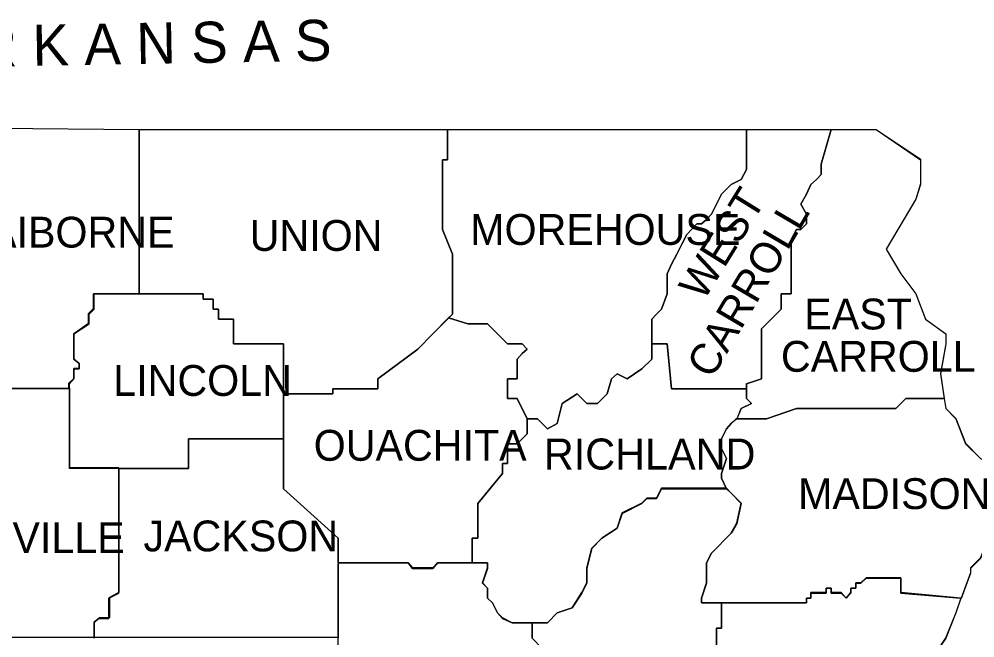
# Model space of a CAD drawing. Extents: x 0.19 to 2.82, y 0.04 to 1.79.
# Drawn here: x 2.2917 to 2.4368, y 1.6727 to 1.7666 of the extents above; entities that cross this region are included whole.
import ezdxf

# ---------------------------------------------------------------- set-up
doc = ezdxf.new("R2010")
doc.units = 0
for name, color, linetype in [('Dist04', 7, 'Continuous'), ('Dist05', 7, 'Continuous'), ('Dist08', 7, 'Continuous'), ('Dist58', 7, 'Continuous'), ('Standard Info', 7, 'Continuous')]:
    doc.layers.add(name, color=color, linetype=linetype)

msp = doc.modelspace()

# ---------------------------------------------------------------- linework, layer by layer
at = {"layer": 'Dist04'}
msp.add_line((2.27282, 1.75017), (2.3099, 1.74983), dxfattribs=at)
for points in [[(2.3099, 1.74983), (2.3099, 1.72492)], [(2.3099, 1.72492), (2.30299, 1.72492), (2.30299, 1.72267), (2.30224, 1.72192), (2.30224, 1.72042), (2.29999, 1.71883), (2.29999, 1.71508), (2.30082, 1.71433), (2.30082, 1.71358), (2.29999, 1.71358), (2.29999, 1.71208), (2.29924, 1.71133), (2.29924, 1.7105)], [(2.29932, 1.71058), (2.29932, 1.6985), (2.30682, 1.6985)], [(2.30682, 1.6985), (2.30682, 1.67958), (2.3054, 1.67883), (2.3054, 1.6765), (2.3054, 1.67575), (2.3039, 1.67575), (2.30307, 1.67508), (2.30307, 1.67275)], [(2.30307, 1.67275), (2.27665, 1.67275)]]:
    msp.add_lwpolyline(points, dxfattribs=at)
at = {"layer": 'Dist05'}
for p, q in [((2.3099, 1.74983), (2.35674, 1.74983)), ((2.35674, 1.74983), (2.40215, 1.74983)), ((2.40215, 1.74983), (2.41499, 1.74983)), ((2.41499, 1.74983), (2.42182, 1.74983))]:
    msp.add_line(p, q, dxfattribs=at)
for points in [[(2.3099, 1.72492), (2.3099, 1.74983)], [(2.42182, 1.74983), (2.42857, 1.74533), (2.42857, 1.74158), (2.42782, 1.73925), (2.42332, 1.73167), (2.42557, 1.72792), (2.42782, 1.72492), (2.42932, 1.72108), (2.4324, 1.71883), (2.4324, 1.71733), (2.43157, 1.71283), (2.43215, 1.709)], [(2.29924, 1.7105), (2.29924, 1.71133), (2.29999, 1.71208), (2.29999, 1.71358), (2.30082, 1.71358), (2.30082, 1.71433), (2.29999, 1.71508), (2.29999, 1.71883), (2.30224, 1.72042), (2.30224, 1.72192), (2.30299, 1.72267), (2.30299, 1.72492), (2.3099, 1.72492)], [(2.30682, 1.6985), (2.29932, 1.6985), (2.29932, 1.71058)], [(2.43215, 1.709), (2.4324, 1.7075), (2.4339, 1.706), (2.4354, 1.70225), (2.43765, 1.69992), (2.43915, 1.69925), (2.44065, 1.69542), (2.43999, 1.69083), (2.43765, 1.68483), (2.43615, 1.68333), (2.43615, 1.68258), (2.43474, 1.67875)], [(2.30307, 1.67275), (2.30307, 1.67508), (2.3039, 1.67575), (2.3054, 1.67575), (2.3054, 1.6765), (2.3054, 1.67883), (2.30682, 1.67958), (2.30682, 1.6985)], [(2.39907, 1.69542), (2.38924, 1.69542), (2.38849, 1.69392), (2.38699, 1.69392), (2.38624, 1.69317), (2.38324, 1.69167), (2.38249, 1.68933), (2.38015, 1.68783), (2.37865, 1.68633), (2.3779, 1.68333), (2.3779, 1.68108), (2.37715, 1.67958), (2.37565, 1.67725), (2.3734, 1.6765), (2.3719, 1.675), (2.36957, 1.675), (2.36807, 1.675), (2.36657, 1.675), (2.36507, 1.67575), (2.36432, 1.6765), (2.36357, 1.678), (2.36282, 1.67875), (2.36282, 1.68025), (2.36207, 1.68108), (2.36282, 1.68333), (2.36282, 1.68408), (2.36049, 1.68408)], [(2.41124, 1.678), (2.39532, 1.678), (2.39532, 1.67875), (2.39607, 1.68108), (2.39607, 1.68258), (2.39607, 1.68408), (2.39682, 1.68558), (2.39982, 1.68858), (2.40065, 1.69017), (2.40132, 1.69317), (2.39982, 1.69467), (2.39907, 1.69542)], [(2.36049, 1.68408), (2.35524, 1.68408), (2.35449, 1.68333), (2.3514, 1.68333), (2.35074, 1.68408), (2.34015, 1.68408)], [(2.34015, 1.684), (2.34015, 1.67275)], [(2.42557, 1.67958), (2.42557, 1.68183), (2.42032, 1.68183), (2.41949, 1.68108), (2.41874, 1.68108), (2.41874, 1.68025), (2.41799, 1.68025), (2.41799, 1.67958), (2.41724, 1.67875), (2.41649, 1.67958), (2.41499, 1.67958), (2.41499, 1.68025), (2.41424, 1.68025), (2.41424, 1.67958), (2.4119, 1.67958), (2.4119, 1.67875), (2.41124, 1.67875), (2.41124, 1.678)], [(2.43465, 1.67875), (2.42557, 1.67958)], [(2.34015, 1.67275), (2.30307, 1.67275)]]:
    msp.add_lwpolyline(points, dxfattribs=at)
at = {"layer": 'Dist08'}
for points in [[(2.30307, 1.67275), (2.27665, 1.67275)], [(2.34015, 1.67275), (2.30307, 1.67275)], [(2.34015, 1.65458), (2.34015, 1.67275)]]:
    msp.add_lwpolyline(points, dxfattribs=at)
at = {"layer": 'Dist58'}
msp.add_line((2.43465, 1.67875), (2.43465, 1.67875), dxfattribs=at)
for points in [[(2.36049, 1.68408), (2.36282, 1.68408), (2.36282, 1.68333), (2.36207, 1.68108), (2.36282, 1.68025), (2.36282, 1.67875), (2.36357, 1.678), (2.36432, 1.6765), (2.36507, 1.67575), (2.36657, 1.675), (2.36807, 1.675), (2.36957, 1.675), (2.3719, 1.675), (2.3734, 1.6765), (2.37565, 1.67725), (2.37715, 1.67958), (2.3779, 1.68108), (2.3779, 1.68333), (2.37865, 1.68633), (2.38015, 1.68783), (2.38249, 1.68933), (2.38324, 1.69167), (2.38624, 1.69317), (2.38699, 1.69392), (2.38849, 1.69392), (2.38924, 1.69542), (2.39907, 1.69542)], [(2.39907, 1.69542), (2.39982, 1.69467), (2.40132, 1.69317), (2.40065, 1.69017), (2.39982, 1.68858), (2.39682, 1.68558), (2.39607, 1.68408), (2.39607, 1.68258), (2.39607, 1.68108), (2.39532, 1.67875), (2.39532, 1.678), (2.41124, 1.678)], [(2.34015, 1.68408), (2.35074, 1.68408), (2.3514, 1.68333), (2.35449, 1.68333), (2.35524, 1.68408), (2.36049, 1.68408)], [(2.34015, 1.67275), (2.34015, 1.684)], [(2.41124, 1.678), (2.41124, 1.67875), (2.4119, 1.67875), (2.4119, 1.67958), (2.41424, 1.67958), (2.41424, 1.68025), (2.41499, 1.68025), (2.41499, 1.67958), (2.41649, 1.67958), (2.41724, 1.67875), (2.41799, 1.67958), (2.41799, 1.68025), (2.41874, 1.68025), (2.41874, 1.68108), (2.41949, 1.68108), (2.42032, 1.68183), (2.42557, 1.68183), (2.42557, 1.67958)], [(2.42557, 1.67958), (2.43465, 1.67875)], [(2.43465, 1.67875), (2.4339, 1.6765), (2.4324, 1.67275), (2.4309, 1.6705), (2.42782, 1.66517), (2.42482, 1.66142), (2.42182, 1.65758), (2.41799, 1.65308), (2.41424, 1.64933), (2.41274, 1.647), (2.40899, 1.63942)], [(2.34015, 1.65458), (2.34015, 1.67275)]]:
    msp.add_lwpolyline(points, dxfattribs=at)
at = {"layer": 'Standard Info'}
for p, q in [((2.27282, 1.75017), (2.3099, 1.74983)), ((2.3099, 1.74983), (2.35674, 1.74983)), ((2.35674, 1.74983), (2.40215, 1.74983)), ((2.40215, 1.74983), (2.41499, 1.74983)), ((2.41499, 1.74983), (2.42182, 1.74983)), ((2.3569, 1.72125), (2.35749, 1.72183)), ((2.40057, 1.70592), (2.40049, 1.70592))]:
    msp.add_line(p, q, dxfattribs=at)
for points in [[(2.3099, 1.74983), (2.3099, 1.72492)], [(2.3099, 1.72492), (2.3099, 1.74983)], [(2.35674, 1.74983), (2.35674, 1.74525), (2.35599, 1.74525), (2.35599, 1.743), (2.35599, 1.73467), (2.35749, 1.73092), (2.35749, 1.72792), (2.35749, 1.72492), (2.35749, 1.72183), (2.35674, 1.72108), (2.35449, 1.71883), (2.35224, 1.7165), (2.34615, 1.712), (2.34615, 1.7105), (2.33932, 1.7105), (2.33932, 1.70975), (2.33182, 1.70975)], [(2.35749, 1.72183), (2.35749, 1.72492), (2.35749, 1.72792), (2.35749, 1.73092), (2.35599, 1.73467), (2.35599, 1.743), (2.35599, 1.74525), (2.35674, 1.74525), (2.35674, 1.74983)], [(2.38774, 1.71733), (2.38774, 1.71883), (2.38774, 1.72108), (2.38849, 1.72183), (2.38924, 1.72258), (2.39007, 1.72492), (2.39007, 1.72792), (2.39074, 1.72942), (2.39157, 1.73092), (2.39232, 1.73242), (2.39307, 1.73392), (2.39457, 1.7355), (2.39532, 1.7355), (2.39607, 1.73617), (2.39682, 1.737), (2.39757, 1.7385), (2.39832, 1.74), (2.39982, 1.7415), (2.40132, 1.74225), (2.40215, 1.74375), (2.40215, 1.74458), (2.40215, 1.74983)], [(2.40215, 1.74983), (2.40215, 1.74458), (2.40215, 1.74375), (2.40132, 1.74225), (2.39982, 1.7415), (2.39832, 1.74), (2.39757, 1.7385), (2.39682, 1.737), (2.39607, 1.73617), (2.39532, 1.7355), (2.39457, 1.7355), (2.39307, 1.73392), (2.39232, 1.73242), (2.39157, 1.73092), (2.39074, 1.72942), (2.39007, 1.72792), (2.39007, 1.72492), (2.38924, 1.72258), (2.38849, 1.72183), (2.38774, 1.72108), (2.38774, 1.71883), (2.38774, 1.71733)], [(2.38774, 1.71733), (2.38774, 1.71883), (2.38774, 1.72108), (2.38849, 1.72183), (2.38924, 1.72258), (2.39007, 1.72492), (2.39007, 1.72792), (2.39074, 1.72942), (2.39157, 1.73092), (2.39232, 1.73242), (2.39307, 1.73392), (2.39457, 1.7355), (2.39532, 1.7355), (2.39607, 1.73617), (2.39682, 1.737), (2.39757, 1.7385), (2.39832, 1.74), (2.39982, 1.7415), (2.40132, 1.74225), (2.40215, 1.74375), (2.40215, 1.74458), (2.40215, 1.74983)], [(2.40074, 1.70608), (2.40132, 1.7075), (2.4029, 1.70825), (2.40215, 1.709), (2.40215, 1.7105), (2.40215, 1.71125), (2.4044, 1.712), (2.4044, 1.71275), (2.4044, 1.7135), (2.4044, 1.71433), (2.4044, 1.71583), (2.4044, 1.71733), (2.4044, 1.71958), (2.40515, 1.72033), (2.4059, 1.72108), (2.40665, 1.72183), (2.4074, 1.72258), (2.4074, 1.72492), (2.4089, 1.72492), (2.4089, 1.73317), (2.40974, 1.73467), (2.4104, 1.73467), (2.41124, 1.7355), (2.41124, 1.737), (2.4104, 1.7385), (2.41124, 1.74), (2.4119, 1.7415), (2.41274, 1.74225), (2.41349, 1.743), (2.41349, 1.74458), (2.41499, 1.74983)], [(2.41499, 1.74983), (2.41349, 1.74458), (2.41349, 1.743), (2.41274, 1.74225), (2.4119, 1.7415), (2.41124, 1.74), (2.4104, 1.7385), (2.41124, 1.737), (2.41124, 1.7355), (2.4104, 1.73467), (2.40974, 1.73467), (2.4089, 1.73317), (2.4089, 1.72492), (2.4074, 1.72492), (2.4074, 1.72258), (2.40665, 1.72183), (2.4059, 1.72108), (2.40515, 1.72033), (2.4044, 1.71958), (2.4044, 1.71733), (2.4044, 1.71583), (2.4044, 1.71433), (2.4044, 1.7135), (2.4044, 1.71275), (2.4044, 1.712), (2.40215, 1.71125), (2.40215, 1.7105)], [(2.42182, 1.74983), (2.42857, 1.74525), (2.42857, 1.7415), (2.42782, 1.73925), (2.42332, 1.73167), (2.42557, 1.72792), (2.42782, 1.72492), (2.42932, 1.72108), (2.4324, 1.71883), (2.4324, 1.71733), (2.43157, 1.71275), (2.43215, 1.709)], [(2.3099, 1.72492), (2.30299, 1.72492), (2.30299, 1.72258), (2.30224, 1.72183), (2.30224, 1.72033), (2.29999, 1.71883), (2.29999, 1.715), (2.30082, 1.71433), (2.30082, 1.7135), (2.29999, 1.7135), (2.29999, 1.712), (2.29924, 1.71125), (2.29924, 1.7105)], [(2.29932, 1.7105), (2.29932, 1.71125), (2.29999, 1.712), (2.29999, 1.7135), (2.30082, 1.7135), (2.30082, 1.71433), (2.29999, 1.715), (2.29999, 1.71883), (2.30232, 1.72033), (2.30232, 1.72183), (2.30307, 1.72258), (2.30307, 1.72492), (2.3099, 1.72492)], [(2.29932, 1.7105), (2.29932, 1.71125), (2.29999, 1.712), (2.29999, 1.7135), (2.30082, 1.7135), (2.30082, 1.71433), (2.29999, 1.715), (2.29999, 1.71883), (2.30232, 1.72033), (2.30232, 1.72183), (2.30307, 1.72258), (2.30307, 1.72492), (2.3099, 1.72492)], [(2.33182, 1.70975), (2.33182, 1.71733), (2.32424, 1.71733), (2.32424, 1.72108), (2.32199, 1.72108), (2.32199, 1.72258), (2.32115, 1.72258), (2.32115, 1.72408), (2.31965, 1.72408), (2.31965, 1.72492), (2.3099, 1.72492)], [(2.3099, 1.72492), (2.31965, 1.72492), (2.31965, 1.72408), (2.32115, 1.72408), (2.32115, 1.72258), (2.32199, 1.72258), (2.32199, 1.72108), (2.32424, 1.72108), (2.32424, 1.71733), (2.33182, 1.71733), (2.33182, 1.70975), (2.33182, 1.70292)], [(2.33182, 1.70975), (2.33932, 1.70975), (2.33932, 1.7105), (2.34615, 1.7105), (2.34615, 1.712), (2.35224, 1.7165), (2.35449, 1.71883), (2.3569, 1.72125)], [(2.3569, 1.72125), (2.35982, 1.72033), (2.36282, 1.72033), (2.36432, 1.71883), (2.36582, 1.71733), (2.36807, 1.71733), (2.36882, 1.7165), (2.36807, 1.71583), (2.36732, 1.715), (2.36732, 1.712), (2.36582, 1.712), (2.36582, 1.709), (2.36732, 1.709), (2.36882, 1.70592), (2.36882, 1.70367), (2.36732, 1.70217), (2.36582, 1.70217), (2.36582, 1.69917), (2.36507, 1.69917), (2.36507, 1.69767), (2.36132, 1.69308), (2.36132, 1.68783), (2.36049, 1.68783), (2.36049, 1.68408)], [(2.36882, 1.70592), (2.36732, 1.709), (2.36582, 1.709), (2.36582, 1.712), (2.36732, 1.712), (2.36732, 1.715), (2.36807, 1.71583), (2.36882, 1.7165), (2.36807, 1.71733), (2.36582, 1.71733), (2.36432, 1.71883), (2.36282, 1.72033), (2.35982, 1.72033), (2.3569, 1.72125)], [(2.38774, 1.71733), (2.38774, 1.715), (2.38624, 1.7135), (2.38399, 1.712), (2.38249, 1.71275), (2.38165, 1.712), (2.38099, 1.70975), (2.37949, 1.70825), (2.3779, 1.70825), (2.3764, 1.70975), (2.37415, 1.70825), (2.3734, 1.70525), (2.3719, 1.70442), (2.3704, 1.70592), (2.36882, 1.70592)], [(2.36882, 1.70592), (2.3704, 1.70592), (2.3719, 1.70442), (2.3734, 1.70525), (2.37415, 1.70825), (2.3764, 1.70975), (2.3779, 1.70825), (2.37949, 1.70825), (2.38099, 1.70975), (2.38165, 1.712), (2.38249, 1.71275), (2.38399, 1.712), (2.38624, 1.7135), (2.38774, 1.715), (2.38774, 1.71733)], [(2.40215, 1.7105), (2.39074, 1.7105), (2.39007, 1.71733), (2.38774, 1.71733)], [(2.38774, 1.71733), (2.39007, 1.71733), (2.39074, 1.7105), (2.40215, 1.7105)], [(2.29924, 1.7105), (2.27765, 1.7105)], [(2.27774, 1.71058), (2.29932, 1.71058)], [(2.29932, 1.71058), (2.29932, 1.6985), (2.30682, 1.6985)], [(2.30682, 1.69842), (2.29932, 1.69842), (2.29932, 1.7105)], [(2.34015, 1.68408), (2.34015, 1.68783), (2.33182, 1.69533), (2.33182, 1.70292), (2.33182, 1.70975)], [(2.40215, 1.7105), (2.40215, 1.709), (2.4029, 1.70825), (2.40132, 1.7075), (2.40065, 1.70592), (2.39982, 1.70525), (2.39907, 1.70442), (2.39832, 1.70292), (2.39832, 1.70217), (2.39832, 1.70142), (2.39907, 1.69992), (2.39832, 1.69767), (2.39832, 1.69692), (2.39907, 1.69533)], [(2.43215, 1.709), (2.42632, 1.709), (2.42482, 1.7075), (2.40974, 1.7075), (2.40515, 1.70592), (2.40049, 1.70592)], [(2.40049, 1.70592), (2.40515, 1.70592), (2.40974, 1.7075), (2.42482, 1.7075), (2.42632, 1.709), (2.43215, 1.709)], [(2.43215, 1.709), (2.4324, 1.7075), (2.4339, 1.70592), (2.4354, 1.70217), (2.43765, 1.69992), (2.43915, 1.69917), (2.44065, 1.69533), (2.43999, 1.69083), (2.43765, 1.68475), (2.43615, 1.68325), (2.43615, 1.6825), (2.43474, 1.67867)], [(2.36049, 1.68408), (2.36049, 1.68783), (2.36132, 1.68783), (2.36132, 1.69308), (2.36507, 1.69767), (2.36507, 1.69917), (2.36582, 1.69917), (2.36582, 1.70217), (2.36732, 1.70217), (2.36882, 1.70367), (2.36882, 1.70592)], [(2.39907, 1.69533), (2.39832, 1.69692), (2.39832, 1.69767), (2.39907, 1.69992), (2.39832, 1.70142), (2.39832, 1.70217), (2.39832, 1.70292), (2.39907, 1.70442), (2.39982, 1.70525), (2.40057, 1.70592)], [(2.33182, 1.70292), (2.3174, 1.70292), (2.3174, 1.69842), (2.30682, 1.69842)], [(2.30682, 1.69842), (2.3174, 1.69842), (2.3174, 1.70292), (2.33182, 1.70292)], [(2.33182, 1.70292), (2.33182, 1.69533), (2.34015, 1.68783), (2.34015, 1.68408)], [(2.30682, 1.6985), (2.30682, 1.67958), (2.3054, 1.67875), (2.3054, 1.6765), (2.3054, 1.67575), (2.3039, 1.67575), (2.30307, 1.675), (2.30307, 1.67267)], [(2.30307, 1.67267), (2.30307, 1.675), (2.30382, 1.67567), (2.30532, 1.67567), (2.30532, 1.6765), (2.30532, 1.67875), (2.30682, 1.6795), (2.30682, 1.69842)], [(2.39907, 1.69533), (2.38924, 1.69533), (2.38849, 1.69383), (2.38699, 1.69383), (2.38624, 1.69308), (2.38324, 1.69158), (2.38249, 1.68933), (2.38015, 1.68783), (2.37865, 1.68625), (2.3779, 1.68325), (2.3779, 1.681), (2.37715, 1.6795), (2.37565, 1.67725), (2.3734, 1.6765), (2.3719, 1.675), (2.36957, 1.675), (2.36807, 1.675), (2.36657, 1.675), (2.36507, 1.67567), (2.36432, 1.6765), (2.36357, 1.678), (2.36282, 1.67875), (2.36282, 1.68025), (2.36207, 1.681), (2.36282, 1.68325), (2.36282, 1.68408), (2.36049, 1.68408)], [(2.36957, 1.675), (2.3719, 1.675), (2.3734, 1.6765), (2.37565, 1.67725), (2.37715, 1.6795), (2.3779, 1.681), (2.3779, 1.68325), (2.37865, 1.68625), (2.38015, 1.68783), (2.38249, 1.68933), (2.38324, 1.69158), (2.38624, 1.69308), (2.38699, 1.69383), (2.38849, 1.69383), (2.38924, 1.69533), (2.39907, 1.69533)], [(2.41124, 1.678), (2.39532, 1.678), (2.39532, 1.67875), (2.39607, 1.681), (2.39607, 1.6825), (2.39607, 1.68408), (2.39682, 1.68558), (2.39982, 1.68858), (2.40065, 1.69008), (2.40132, 1.69308), (2.39982, 1.69467), (2.39907, 1.69533)], [(2.39907, 1.69533), (2.39982, 1.69467), (2.40132, 1.69308), (2.40065, 1.69008), (2.39982, 1.68858), (2.39682, 1.68558), (2.39607, 1.68408), (2.39607, 1.6825), (2.39607, 1.681), (2.39532, 1.67875), (2.39532, 1.678), (2.39832, 1.678)], [(2.36049, 1.68408), (2.35524, 1.68408), (2.35449, 1.68325), (2.3514, 1.68325), (2.35074, 1.68408), (2.34015, 1.68408)], [(2.34015, 1.68408), (2.35074, 1.68408), (2.3514, 1.68325), (2.35449, 1.68325), (2.35524, 1.68408), (2.36282, 1.68408), (2.36282, 1.68325), (2.36207, 1.681), (2.36282, 1.68025), (2.36282, 1.67875), (2.36357, 1.678), (2.36432, 1.6765), (2.36507, 1.67567), (2.36657, 1.675), (2.36807, 1.675), (2.36957, 1.675)], [(2.34015, 1.68392), (2.34015, 1.67267)], [(2.34015, 1.67267), (2.34015, 1.68383)], [(2.42557, 1.6795), (2.42557, 1.68175), (2.42032, 1.68175), (2.41949, 1.681), (2.41874, 1.681), (2.41874, 1.68025), (2.41799, 1.68025), (2.41799, 1.6795), (2.41724, 1.67875), (2.41649, 1.6795), (2.41499, 1.6795), (2.41499, 1.68025), (2.41424, 1.68025), (2.41424, 1.6795), (2.4119, 1.6795), (2.4119, 1.67875), (2.41124, 1.67875), (2.41124, 1.678)], [(2.41124, 1.678), (2.41124, 1.67875), (2.4119, 1.67875), (2.4119, 1.6795), (2.41424, 1.6795), (2.41424, 1.68025), (2.41499, 1.68025), (2.41499, 1.6795), (2.41649, 1.6795), (2.41724, 1.67875), (2.41799, 1.6795), (2.41799, 1.68025), (2.41874, 1.68025), (2.41874, 1.681), (2.41949, 1.681), (2.42032, 1.68175), (2.42557, 1.68175), (2.42557, 1.6795)], [(2.43465, 1.67875), (2.42557, 1.6795)], [(2.42557, 1.6795), (2.43465, 1.67875)], [(2.39832, 1.678), (2.39832, 1.67417), (2.39757, 1.67417), (2.39757, 1.66967), (2.39832, 1.66892), (2.39832, 1.66742), (2.39757, 1.66742), (2.39757, 1.66358), (2.39832, 1.66208), (2.39832, 1.66058), (2.39757, 1.65983), (2.39682, 1.65908), (2.39682, 1.65758), (2.39757, 1.656), (2.39682, 1.6545), (2.39607, 1.65383), (2.39532, 1.65383), (2.39457, 1.653), (2.39307, 1.653), (2.39307, 1.6515)], [(2.39757, 1.66967), (2.39757, 1.67417), (2.39832, 1.67417), (2.39832, 1.678)], [(2.39832, 1.678), (2.41124, 1.678)], [(2.43465, 1.67875), (2.4339, 1.6765), (2.4324, 1.67267), (2.4309, 1.67042), (2.42782, 1.66508), (2.42482, 1.66133), (2.42182, 1.65758), (2.41799, 1.653), (2.41424, 1.64925), (2.41274, 1.647), (2.40899, 1.63942)], [(2.36957, 1.675), (2.36957, 1.67267), (2.37107, 1.67117), (2.37107, 1.66892), (2.3704, 1.66892), (2.36882, 1.66817), (2.36807, 1.66742), (2.36807, 1.66592), (2.36882, 1.66508), (2.36957, 1.66358), (2.36957, 1.66133), (2.36957, 1.65908), (2.3704, 1.65833)], [(2.36957, 1.67267), (2.36957, 1.675)]]:
    msp.add_lwpolyline(points, dxfattribs=at)

# ---------------------------------------------------------------- texts
for s, height, rotation, p in [('A R K A N S A S', 0.0062368, 1.0059, (2.27755, 1.7592)), ('WEST', 0.004679, 58.1411, (2.3956, 1.72366)), ('CARROLL', 0.004679, 59.4887, (2.39686, 1.71184))]:
    msp.add_text(s, height=height, rotation=rotation, dxfattribs=at).set_placement(p)
for s, height, p in [('MOREHOUSE', 0.004679, (2.36018, 1.73233)), ('CLAIBORNE', 0.004679, (2.27913, 1.73192)), ('UNION', 0.004679, (2.3267, 1.73142)), ('EAST', 0.004679, (2.4109, 1.7195)), ('CARROLL', 0.004679, (2.40736, 1.71308)), ('LINCOLN', 0.004679, (2.30599, 1.70942)), ('OUACHITA', 0.004679, (2.33642, 1.69958)), ('RICHLAND', 0.0047, (2.37136, 1.69825)), ('MADISON', 0.004679, (2.40996, 1.69225)), ('JACKSON', 0.004679, (2.31058, 1.68583)), ('BIENVILLE', 0.004679, (2.27608, 1.68558))]:
    msp.add_text(s, height=height, dxfattribs=at).set_placement(p)

doc.saveas('drawing.dxf')
